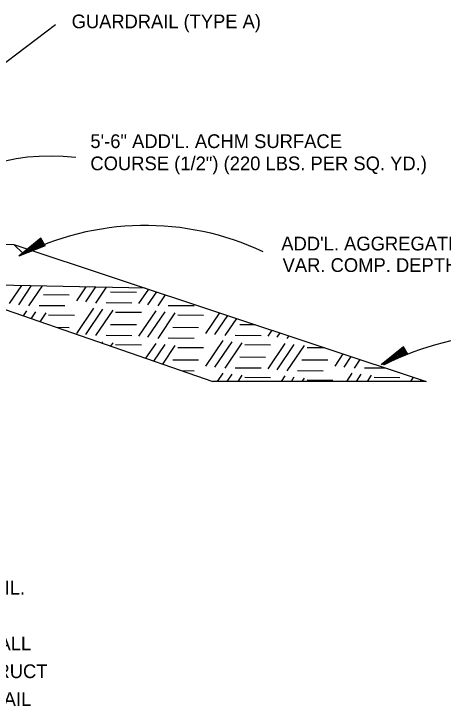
# Model space of a CAD drawing. Extents: x 1926836 to 1933254, y 596317 to 604524.
# Drawn here: x 1928757.8 to 1928945.1, y 602420.9 to 602723 of the extents above; entities that cross this region are included whole.
import ezdxf

# ---------------------------------------------------------------- set-up
doc = ezdxf.new("R2010")
doc.units = 0
doc.layers.add('Default', color=7, linetype='Continuous')
doc.layers.add('R_Annotation', color=7, linetype='Continuous')

msp = doc.modelspace()

# ---------------------------------------------------------------- linework, layer by layer
at = {"layer": 'Default'}
for p, q in [((1928706.94, 602666.13), (1928775.96, 602718.29)), ((1928623.71, 602627.76), (1928757.8, 602622.39)), ((1928769.61, 602625.01), (1928759.91, 602617.27)), ((1928769.79, 602624.72), (1928761.7, 602618.28)), ((1928769.93, 602624.45), (1928763.51, 602619.35)), ((1928770.08, 602624.21), (1928765.28, 602620.38)), ((1928770.23, 602623.91), (1928767.07, 602621.41)), ((1928770.84, 602622.86), (1928767.07, 602621.41)), ((1928770.4, 602623.64), (1928768.88, 602622.44)), ((1928770.69, 602623.15), (1928768.88, 602622.44)), ((1928771.48, 602621.8), (1928769.61, 602625.01)), ((1928757.8, 602622.39), (1928937.68, 602562.6)), ((1928757.8, 602622.39), (1928762.02, 602618.2)), ((1928771.48, 602621.8), (1928759.91, 602617.27)), ((1928771.31, 602622.07), (1928761.7, 602618.28)), ((1928771.13, 602622.34), (1928763.51, 602619.35)), ((1928770.99, 602622.59), (1928765.28, 602620.38)), ((1928423.27, 602611.17), (1928815.02, 602603.38)), ((1928721.07, 602605.25), (1928844.61, 602562.6)), ((1928927.85, 602577.62), (1928918.14, 602569.87)), ((1928929.71, 602574.41), (1928927.85, 602577.62)), ((1928928.02, 602577.32), (1928919.93, 602570.88)), ((1928929.54, 602574.68), (1928919.93, 602570.88)), ((1928928.17, 602577.05), (1928921.75, 602571.96)), ((1928929.37, 602574.95), (1928921.75, 602571.96)), ((1928928.31, 602576.81), (1928923.51, 602572.99)), ((1928929.22, 602575.19), (1928923.51, 602572.99)), ((1928928.46, 602576.51), (1928925.3, 602574.01)), ((1928929.07, 602575.46), (1928925.3, 602574.01)), ((1928928.63, 602576.24), (1928927.11, 602575.04)), ((1928928.92, 602575.75), (1928927.11, 602575.04)), ((1928929.71, 602574.41), (1928918.14, 602569.87)), ((1928937.68, 602562.6), (1928844.61, 602562.6)), ((1928937.15, 602562.6), (1928937.29, 602562.73)), ((1928937.59, 602562.63), (1928937.62, 602562.6))]:
    msp.add_line(p, q, dxfattribs=at)
for centre, radius in [((1928815.19, 602509.39), 121.21), ((1928974.6, 602461.32), 121.72)]:
    msp.add_arc(centre, radius, 64.8876, 117.1378, dxfattribs=at)
msp.add_ellipse((1928779.93, 602620.52), major_axis=(-60.55, 7.39), ratio=0.655798, start_param=4.712389, end_param=6.093533, dxfattribs=at)
at = {"layer": 'R_Annotation'}
for p, q in [((1928755.96, 602596.5), (1928761.32, 602604.45)), ((1928759.93, 602596.03), (1928765.55, 602604.36)), ((1928764.36, 602595.57), (1928770.23, 602604.27)), ((1928785.2, 602597.7), (1928789.38, 602603.89)), ((1928789.17, 602597.23), (1928793.61, 602603.8)), ((1928793.61, 602596.77), (1928798.29, 602603.71)), ((1928812.35, 602596.5), (1928816.63, 602602.84)), ((1928770.73, 602600.47), (1928781.99, 602600.37)), ((1928799.97, 602601.67), (1928811.24, 602601.58)), ((1928816.32, 602596.03), (1928820.12, 602601.68)), ((1928820.75, 602595.57), (1928824, 602600.39)), ((1928768.79, 602595.76), (1928780.05, 602595.66)), ((1928798.04, 602596.96), (1928809.3, 602596.87)), ((1928825.18, 602595.76), (1928836.44, 602595.66)), ((1928761.93, 602591.14), (1928763.44, 602593.38)), ((1928765.4, 602589.94), (1928767.41, 602592.91)), ((1928785.2, 602583.49), (1928792.68, 602594.58)), ((1928789.17, 602583.03), (1928796.65, 602594.11)), ((1928793.61, 602582.57), (1928801.08, 602593.65)), ((1928802.19, 602592.82), (1928813.45, 602592.73)), ((1928812.35, 602582.29), (1928819.82, 602593.38)), ((1928816.32, 602581.83), (1928823.79, 602592.91)), ((1928769.25, 602588.61), (1928771.84, 602592.45)), ((1928772.95, 602591.62), (1928784.21, 602591.53)), ((1928820.75, 602581.37), (1928828.22, 602592.45)), ((1928829.33, 602591.62), (1928840.59, 602591.53)), ((1928841.59, 602583.49), (1928847.68, 602592.52)), ((1928845.56, 602583.03), (1928851.17, 602591.35)), ((1928849.99, 602582.57), (1928855.05, 602590.07)), ((1928799.97, 602587.46), (1928811.24, 602587.37)), ((1928856.36, 602587.46), (1928863.04, 602587.41)), ((1928776.18, 602586.22), (1928781.99, 602586.17)), ((1928827.12, 602586.26), (1928838.38, 602586.17)), ((1928868.73, 602582.29), (1928870.51, 602584.93)), ((1928872.7, 602581.83), (1928874.01, 602583.76)), ((1928798.04, 602582.75), (1928809.3, 602582.66)), ((1928825.18, 602581.55), (1928836.44, 602581.46)), ((1928854.42, 602582.75), (1928865.68, 602582.66)), ((1928877.13, 602581.37), (1928877.88, 602582.48)), ((1928796.24, 602579.3), (1928796.65, 602579.91)), ((1928800.08, 602577.97), (1928801.08, 602579.45)), ((1928802.19, 602578.62), (1928813.45, 602578.53)), ((1928815.43, 602572.67), (1928819.82, 602579.17)), ((1928818.91, 602571.47), (1928823.79, 602578.71)), ((1928822.75, 602570.14), (1928828.22, 602578.25)), ((1928841.59, 602569.29), (1928849.07, 602580.37)), ((1928845.56, 602568.83), (1928853.04, 602579.91)), ((1928849.99, 602568.37), (1928857.47, 602579.45)), ((1928858.58, 602578.62), (1928869.84, 602578.53)), ((1928868.73, 602568.09), (1928876.21, 602579.17)), ((1928872.7, 602567.63), (1928880.18, 602578.71)), ((1928877.13, 602567.17), (1928884.61, 602578.25)), ((1928829.33, 602577.42), (1928840.59, 602577.33)), ((1928885.72, 602577.42), (1928893.28, 602577.36)), ((1928897.98, 602569.29), (1928901.56, 602574.6)), ((1928827.12, 602572.06), (1928838.38, 602571.97)), ((1928856.36, 602573.26), (1928867.62, 602573.17)), ((1928883.5, 602572.06), (1928894.76, 602571.97)), ((1928901.95, 602568.83), (1928905.06, 602573.44)), ((1928906.38, 602568.37), (1928908.93, 602572.15)), ((1928854.42, 602568.55), (1928865.68, 602568.46)), ((1928910.81, 602568.55), (1928919.99, 602568.48)), ((1928830.97, 602567.3), (1928836.44, 602567.26)), ((1928846.66, 602562.6), (1928849.07, 602566.17)), ((1928850.94, 602562.6), (1928853.04, 602565.71)), ((1928881.56, 602567.35), (1928892.83, 602567.26)), ((1928903.04, 602562.6), (1928905.45, 602566.17)), ((1928907.32, 602562.6), (1928909.42, 602565.71)), ((1928855.68, 602562.6), (1928857.47, 602565.25)), ((1928858.58, 602564.42), (1928869.84, 602564.32)), ((1928874.61, 602562.6), (1928876.21, 602564.97)), ((1928878.89, 602562.6), (1928880.18, 602564.51)), ((1928883.63, 602562.6), (1928884.61, 602564.05)), ((1928885.72, 602563.21), (1928896.98, 602563.12)), ((1928912.07, 602562.6), (1928913.85, 602565.25)), ((1928914.96, 602564.42), (1928926.22, 602564.32)), ((1928930.99, 602562.6), (1928932.22, 602564.41)), ((1928935.27, 602562.6), (1928935.72, 602563.25))]:
    msp.add_line(p, q, dxfattribs=at)

# ---------------------------------------------------------------- texts
at = {"layer": 'Default'}
for s, height, p in [('GUARDRAIL (TYPE A)', 5.9751, (1928783.02, 602716.68)), ('5\'-6" ADD\'L. ACHM SURFACE ', 6, (1928791.18, 602664.4)), ('COURSE (1/2") (220 LBS. PER SQ. YD.)', 6, (1928791.18, 602654.71)), ("ADD'L. AGGREGATE BASE COURSE (CLASS 7)", 6, (1928874.49, 602619.72)), ('VAR. COMP. DEPTH (VAR. TONS/STA.)', 6, (1928875.05, 602610.33)), ('   1.  REFER TO STD. DWG. GR-9A FOR SLOPE REQUIREMENTS BEHIND GUARDRAIL.', 6, (1928434.12, 602469.55)), ('   2.  FOR HORIZONTAL AND VERTICAL CONTROL, THE GUARDRAIL WIDENING SHALL', 6, (1928434.12, 602445.25)), ('       MATCH THE SLOPES AND GRADES OF THE MAIN LANE SHOULDERS.  CONSTRUCT', 6, (1928434.12, 602433.1)), ('       BRIDGE APPROACH AND MAIN LANE TRANSITIONS BEFORE PAVING GUARDRAIL ', 6, (1928434.12, 602420.95))]:
    msp.add_text(s, height=height, rotation=360, dxfattribs=at).set_placement(p)

doc.saveas('drawing.dxf')
